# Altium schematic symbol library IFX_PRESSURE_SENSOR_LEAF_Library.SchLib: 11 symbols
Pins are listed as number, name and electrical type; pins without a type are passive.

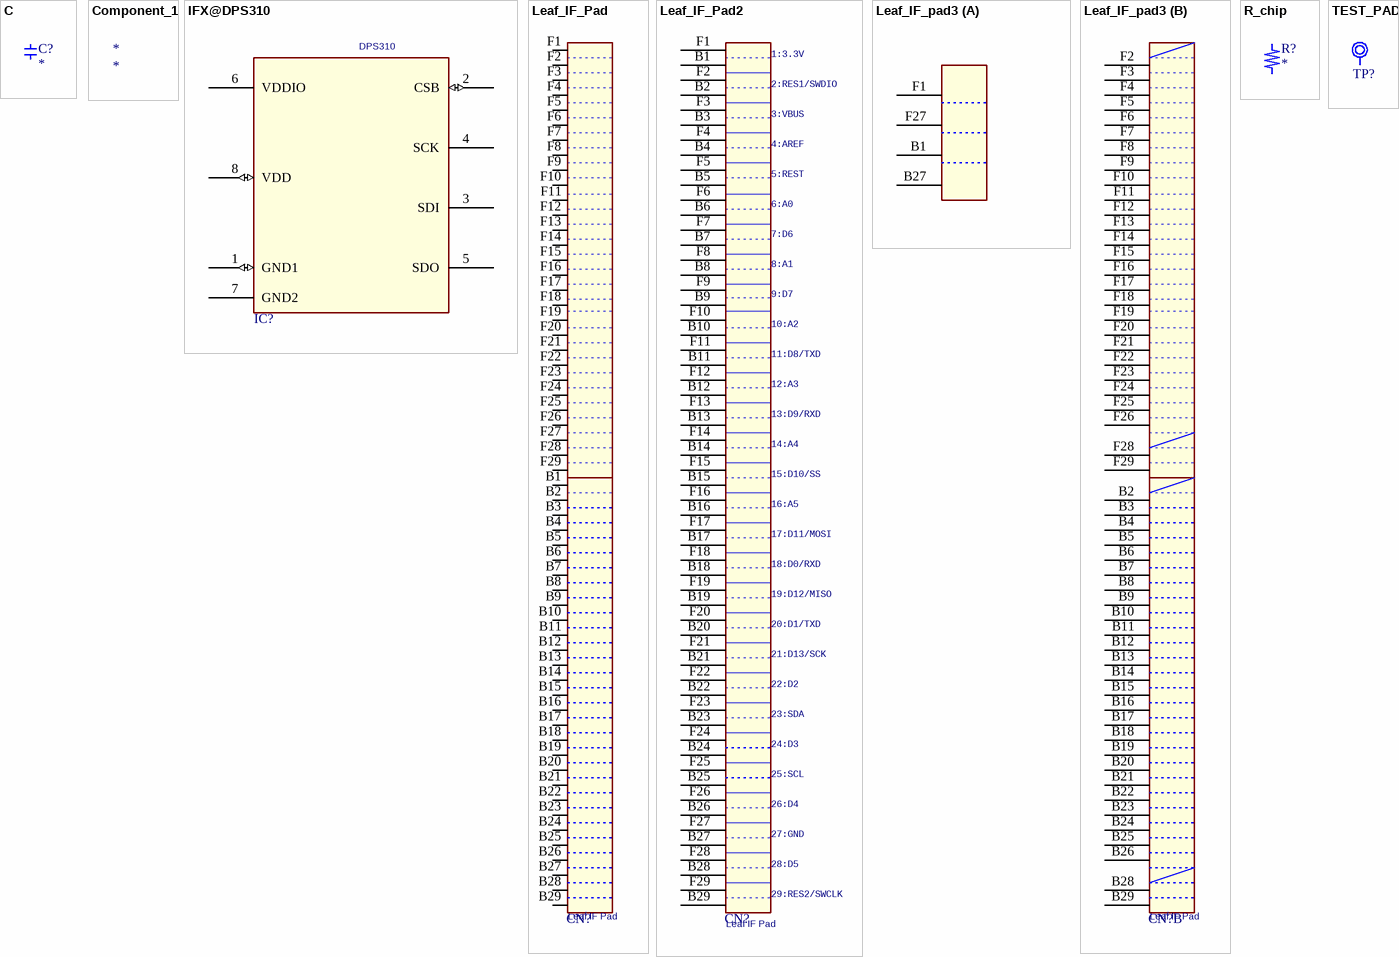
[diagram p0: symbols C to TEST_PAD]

## C
designator C?
pins: 1, 2

## Component_1
designator *

## IFX@DPS310
designator IC?, comment DPS310
pins: 1 GND1 (io), 2 CSB (io), 3 SDI (power), 4 SCK (power), 5 SDO (power), 6 VDDIO (power), 7 GND2 (power), 8 VDD (io)

## Leaf_IF_Pad
designator CN?, comment Leaf IF Pad
pins: B1 30, B2 31, B3 32, B4 33, B5 34, B6 35, B7 36, B8 37, B9 38, B10 39, B11 40, B12 41, B13 42, B14 43, B15 44, B16 45, B17 46, B18 47, B19 48, B20 49, B21 50, B22 51, B23 52, B24 53, B25 54, B26 55, B27 56, B28 57, B29 58, F1 1, F2 2, F3 3, F4 4, F5 5, F6 6, F7 7, F8 8, F9 9, F10 10, F11 11, F12 12, F13 13, F14 14, F15 15, F16 16, F17 17, F18 18, F19 19, F20 20, F21 21, F22 22, F23 23, F24 24, F25 25, F26 26, F27 27, F28 28, F29 29

## Leaf_IF_Pad2
designator CN?, comment Leaf IF Pad
pins: B1 30, B2 31, B3 32, B4 33, B5 34, B6 35, B7 36, B8 37, B9 38, B10 39, B11 40, B12 41, B13 42, B14 43, B15 44, B16 45, B17 46, B18 47, B19 48, B20 49, B21 50, B22 51, B23 52, B24 53, B25 54, B26 55, B27 56, B28 57, B29 58, F1 1, F2 2, F3 3, F4 4, F5 5, F6 6, F7 7, F8 8, F9 9, F10 10, F11 11, F12 12, F13 13, F14 14, F15 15, F16 16, F17 17, F18 18, F19 19, F20 20, F21 21, F22 22, F23 23, F24 24, F25 25, F26 26, F27 27, F28 28, F29 29

## Leaf_IF_pad3
designator CN?, comment Leaf IF Pad
part A pins: B1 30, B27 56, F1 1, F27 27
part B pins: B2 31, B3 32, B4 33, B5 34, B6 35, B7 36, B8 37, B9 38, B10 39, B11 40, B12 41, B13 42, B14 43, B15 44, B16 45, B17 46, B18 47, B19 48, B20 49, B21 50, B22 51, B23 52, B24 53, B25 54, B26 55, B28 57, B29 58, F2 2, F3 3, F4 4, F5 5, F6 6, F7 7, F8 8, F9 9, F10 10, F11 11, F12 12, F13 13, F14 14, F15 15, F16 16, F17 17, F18 18, F19 19, F20 20, F21 21, F22 22, F23 23, F24 24, F25 25, F26 26, F28 28, F29 29

## R_chip
designator R?
pins: 1, 2

## TEST_PAD
designator TP?, comment ST-1-2  (value not drawn)
pins: 1

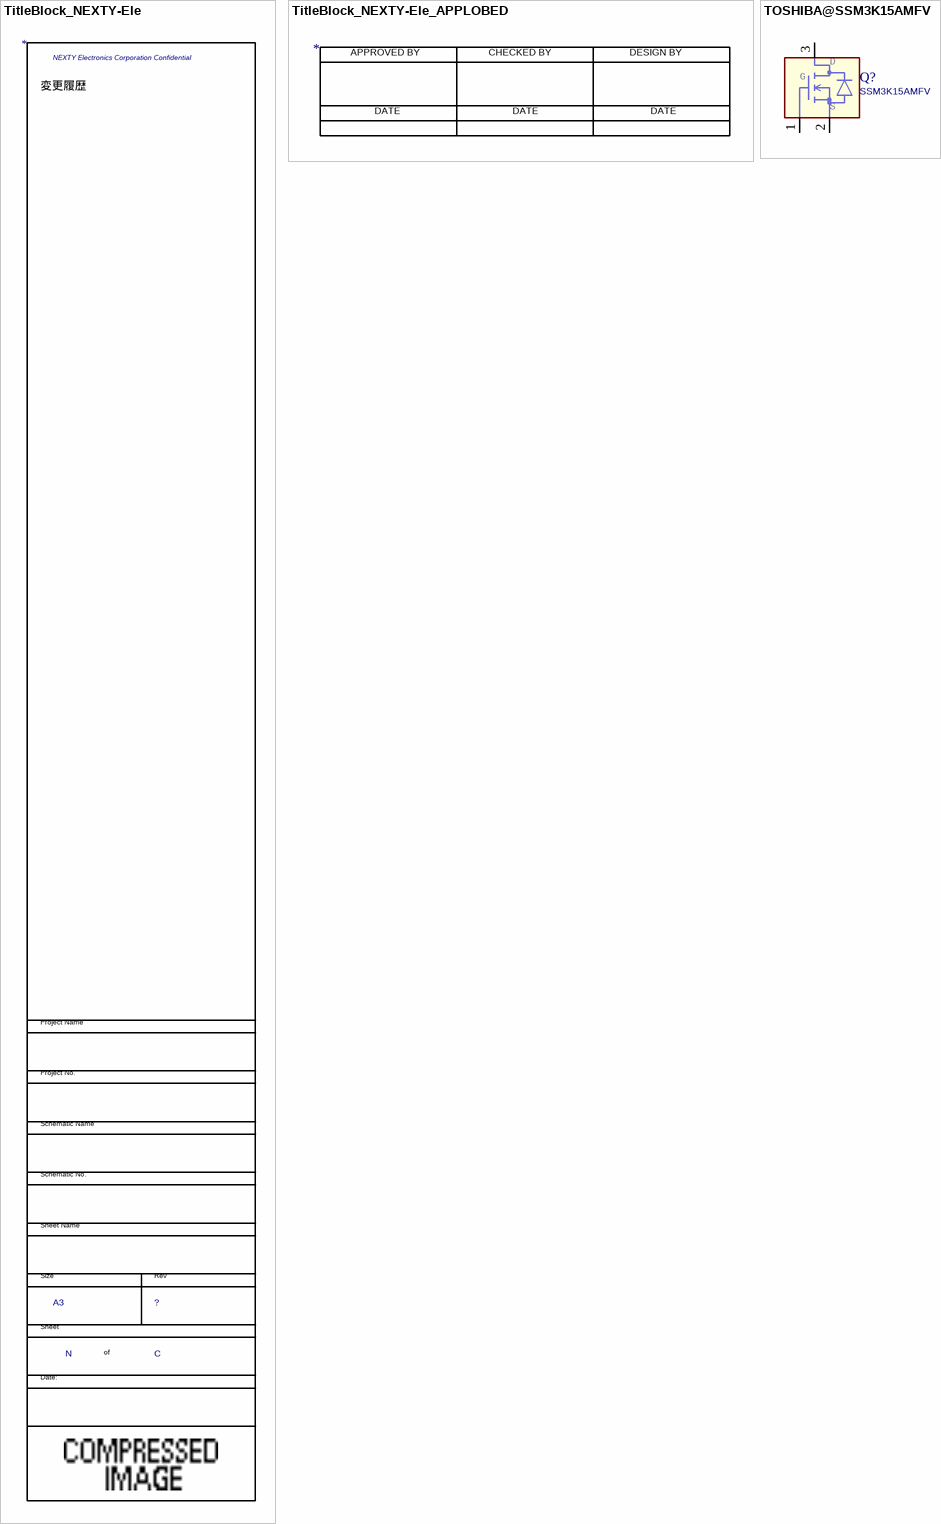
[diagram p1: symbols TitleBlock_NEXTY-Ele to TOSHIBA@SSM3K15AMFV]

## TitleBlock_NEXTY-Ele
designator *  Confidential: NEXTY Electronics Corporation Confidential  Page Size: A3  Page Number: N  Page Count: C  (graphical)
Sample: 例; Histry_First: 完成___Rev1.0; Date2: △△△△年△△月△△日; RevChange: Rev1.0 → 1.1; Histry: B-3_Net___PG0 → PG1; date_drawn: (     /    /   )

## TitleBlock_NEXTY-Ele_APPLOBED
designator *  (graphical)
Sample: 例; Histry_First: 完成___Rev1.0; Date2: △△△△年△△月△△日; RevChange: Rev1.0 → 1.1; Histry: B-3_Net___PG0 → PG1; Page Size: A; Page Number: N; Page Count: C; date_drawn: (     /    /   )

## TOSHIBA@SSM3K15AMFV
designator Q?, comment SSM3K15AMFV
footprint SOT23
pins: 1 G, 2 S, 3 D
